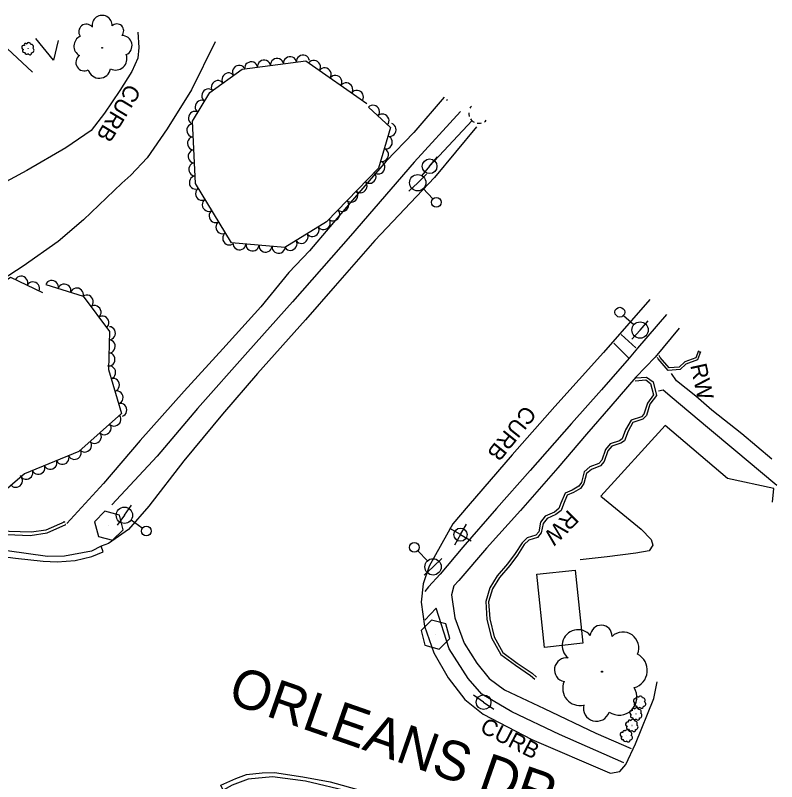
# Model space of a CAD drawing. Extents: x 1722896 to 1754269, y 648279 to 666297.
# Drawn here: x 1726702.6 to 1726935.6, y 658428.6 to 658663.1 of the extents above; entities that cross this region are included whole.
import ezdxf

# ---------------------------------------------------------------- set-up
doc = ezdxf.new("R2010")
doc.units = 0
for name, color, linetype in [('DESIGN - CENTERLINE - Proposed Text', 7, 'Continuous'), ('DESIGN - CONTOURS - Intermediate with optional Text', 7, 'Continuous'), ('DESIGN - PUBLIC HEARING - Shapes', 7, 'Continuous'), ('DESIGN - SCRATCH - User 1', 7, 'Continuous'), ('DESIGN - SHEET - Linework', 7, 'Continuous'), ('SURVEY - CENTERLINE - Preliminary Text', 7, 'Continuous'), ('SURVEY - DTM - Breaklines', 7, 'Continuous'), ('SURVEY - VEGETATION - Features with Text', 7, 'Continuous')]:
    doc.layers.add(name, color=color, linetype=linetype)

msp = doc.modelspace()

# ---------------------------------------------------------------- linework, layer by layer
at = {"layer": 'DESIGN - CENTERLINE - Proposed Text'}
for points in [[(1726696.9, 658655.81), (1726707.9, 658645.77)], [(1726833.89, 658638.08), (1726824.52, 658627.33), (1726816.14, 658618.55), (1726805.08, 658605.71), (1726792.64, 658591.1), (1726786.35, 658584.38), (1726777.69, 658573.93), (1726766.08, 658561.08), (1726754.24, 658548.1), (1726740.82, 658533.01), (1726729.63, 658519.78), (1726718.39, 658507.62)], [(1726834.86, 658637.31), (1726834.61, 658637.03)], [(1726888.06, 658565.4), (1726892.53, 658561.41)], [(1726890.43, 658558.05), (1726885.77, 658562.76)], [(1726911.9, 658560.11), (1726912.32, 658560.16)], [(1726934.1, 658527.29), (1726924.94, 658535.03), (1726915.75, 658542.24), (1726910.86, 658546.55), (1726904.99, 658551.21), (1726903.39, 658553.54)], [(1726899.44, 658548.2), (1726900.89, 658548.51), (1726903.67, 658546.19), (1726914.41, 658537.08), (1726923.14, 658529.86), (1726930.64, 658523.49), (1726935.61, 658519.37)], [(1726526.59, 658537.1), (1726525.3, 658537.11), (1726526.32, 658532.09), (1726527.85, 658528.94), (1726529.41, 658527.23), (1726533.34, 658525.23), (1726537.45, 658524.23), (1726556.14, 658522.16), (1726579.74, 658519.63), (1726602.55, 658516.42), (1726627.84, 658513.39), (1726649.7, 658510.72), (1726668.06, 658507.89), (1726688.75, 658505.07), (1726697.61, 658504.33), (1726707.12, 658503.88), (1726712.3, 658504.74), (1726718.03, 658507.32), (1726717.99, 658507.33)], [(1726717.73, 658508.11), (1726711.99, 658505.58), (1726707.59, 658504.91), (1726697.15, 658505.29), (1726677.53, 658507.38), (1726658.01, 658510.49), (1726632.24, 658514.13), (1726615.96, 658515.97), (1726595.56, 658518.62), (1726575.17, 658521.25), (1726552.96, 658523.64), (1726537.3, 658525.46), (1726532.61, 658526.65), (1726528.77, 658529.28), (1726527.23, 658532.59), (1726526.67, 658535.52), (1726526.59, 658537.1), (1726526.75, 658537.07)], [(1726717.33, 658508.17), (1726717.73, 658508.11)]]:
    msp.add_lwpolyline(points, dxfattribs=at)
msp.add_lwpolyline([(1726873.9, 658493.35), (1726876.3, 658470.92), (1726864.6, 658469.66), (1726862.19, 658492.1)], close=True, dxfattribs=at)
at = {"layer": 'DESIGN - CONTOURS - Intermediate with optional Text'}
for q in [(1726835.6, 658506.04), (1726840.72, 658507.42), (1726836.98, 658500.92), (1726842.09, 658502.3)]:
    msp.add_line((1726838.85, 658504.17), q, dxfattribs=at)
msp.add_circle((1726838.85, 658504.17), 2, dxfattribs=at)
at = {"layer": 'DESIGN - PUBLIC HEARING - Shapes'}
for p, q in [((1726731.17, 658506.92), (1726731.17, 658506.92)), ((1726831.13, 658473.6), (1726831.13, 658473.6))]:
    msp.add_line(p, q, dxfattribs=at)
for points in [[(1726734.44, 658510.18), (1726729.98, 658511.36), (1726726.81, 658508.13), (1726728.02, 658503.64), (1726732.37, 658502.48), (1726735.65, 658505.69), (1726734.44, 658510.18)], [(1726834.39, 658476.86), (1726829.93, 658478.04), (1726826.76, 658474.81), (1726827.97, 658470.32), (1726832.32, 658469.16), (1726835.6, 658472.37), (1726834.39, 658476.86)]]:
    msp.add_lwpolyline(points, dxfattribs=at)
at = {"layer": 'DESIGN - SCRATCH - User 1'}
for points in [[(1726912.32, 658560.16), (1726911.35, 658557.68), (1726907.83, 658556.38), (1726906.08, 658554.73), (1726902.45, 658554.46), (1726899.37, 658557.98), (1726899.16, 658558.38)], [(1726911.68, 658560.49), (1726910.83, 658558.29), (1726907.46, 658557.04), (1726905.78, 658555.46), (1726902.75, 658555.25), (1726899.95, 658558.44), (1726899.67, 658558.98)], [(1726892.29, 658551.26), (1726895.55, 658551.55), (1726897.02, 658550.49), (1726897.92, 658546.95), (1726896.05, 658544.47), (1726895, 658541.05), (1726894.2, 658540.23), (1726891.04, 658539.21), (1726889.36, 658536.22), (1726888.37, 658533.48), (1726887.5, 658532.9), (1726884.7, 658531.96), (1726883.2, 658530.28), (1726882.06, 658527.01), (1726881.2, 658525.95), (1726878.48, 658524.9), (1726876.65, 658523.38), (1726875.87, 658520.14), (1726875.04, 658518.99), (1726873.04, 658517.81), (1726870.85, 658516.84), (1726869.59, 658513.81), (1726868.93, 658512.13), (1726867.58, 658511.05), (1726864.81, 658509.81), (1726863.38, 658507.97), (1726862.79, 658505.08), (1726861.92, 658504.04), (1726859.27, 658503.21), (1726857.73, 658501.64), (1726855.61, 658498.4), (1726853.26, 658495.22), (1726850.07, 658491.59), (1726847.83, 658487.92), (1726846.57, 658483.71), (1726846.95, 658478.24), (1726848.35, 658472.57), (1726851.15, 658467.5), (1726855.65, 658464.18), (1726860.24, 658461.09), (1726861.6, 658459.91)], [(1726892.48, 658552.13), (1726895.79, 658552.42), (1726897.79, 658550.97), (1726898.81, 658546.73), (1726896.81, 658544.09), (1726895.74, 658540.61), (1726894.65, 658539.49), (1726891.6, 658538.51), (1726890.12, 658535.87), (1726889.06, 658532.94), (1726887.87, 658532.14), (1726885.18, 658531.23), (1726883.94, 658529.84), (1726882.8, 658526.6), (1726881.72, 658525.25), (1726878.9, 658524.16), (1726877.4, 658522.91), (1726876.64, 658519.79), (1726875.62, 658518.35), (1726873.42, 658517.06), (1726871.5, 658516.21), (1726870.36, 658513.5), (1726869.63, 658511.61), (1726868.01, 658510.33), (1726865.35, 658509.13), (1726864.16, 658507.61), (1726863.56, 658504.7), (1726862.4, 658503.31), (1726859.71, 658502.46), (1726858.38, 658501.11), (1726856.3, 658497.92), (1726853.91, 658494.7), (1726850.74, 658491.09), (1726848.6, 658487.58), (1726847.41, 658483.61), (1726847.79, 658478.37), (1726849.14, 658472.88), (1726851.8, 658468.07), (1726856.14, 658464.87), (1726860.76, 658461.76), (1726862.15, 658460.55)]]:
    msp.add_lwpolyline(points, dxfattribs=at)
at = {"layer": 'SURVEY - CENTERLINE - Preliminary Text'}
for points in [[(1726740.07, 658658), (1726740.44, 658653.35), (1726740.1, 658650.03), (1726738.23, 658645.95), (1726734.54, 658640.16), (1726729.86, 658633.24), (1726725.83, 658627.86), (1726718.06, 658622.62), (1726706.13, 658615.65), (1726695.86, 658610.15), (1726692.04, 658608.92), (1726690.74, 658609.12)], [(1726714.24, 658649.46), (1726708.85, 658656.09)], [(1726715.74, 658655.45), (1726714.24, 658649.46)], [(1726763.79, 658655.03), (1726756.5, 658640.29), (1726749.1, 658628.45), (1726742.99, 658619.54), (1726737.98, 658614.22), (1726735.22, 658611.72)], [(1726838.81, 658633.73), (1726824.62, 658618.22), (1726805.15, 658595.69), (1726787.42, 658575.49), (1726773.75, 658560.12), (1726758.4, 658542.77), (1726745.98, 658528.23), (1726732.13, 658513.34)], [(1726843.77, 658628.99), (1726830.89, 658613.54), (1726812.58, 658594.26), (1726800.45, 658580.34), (1726791.4, 658569.89), (1726776.7, 658553.5), (1726765.99, 658541.04), (1726754.22, 658526.72), (1726743.48, 658512.94), (1726737.19, 658505.75), (1726731.1, 658501.44)], [(1726735.22, 658611.72), (1726723.43, 658600.52), (1726715.74, 658593.91), (1726705, 658586.32), (1726692.08, 658577.96), (1726681.62, 658571.8), (1726674.06, 658568.05), (1726664.58, 658564.76), (1726645.61, 658560.03), (1726630.05, 658557.08), (1726616.29, 658555.5), (1726597.87, 658553.98), (1726580.16, 658553.27), (1726563.62, 658552.66), (1726547.63, 658552.96), (1726536.58, 658553.02), (1726533.49, 658553.17)], [(1726896.83, 658576.17), (1726882.61, 658559.91), (1726867.71, 658543.42), (1726854.66, 658528.61), (1726841.19, 658513.04), (1726836.46, 658507.47), (1726829.25, 658494.49), (1726827.38, 658489.13), (1726826.83, 658483.54), (1726827.85, 658476.11), (1726830.67, 658468.03), (1726835.07, 658460.38), (1726840.18, 658453.68), (1726845.83, 658449.2), (1726860.63, 658441.42), (1726884.49, 658431.28), (1726884.8, 658431.13)], [(1726901.89, 658571.58), (1726892.99, 658561.26), (1726890.45, 658558.24), (1726881.99, 658548.51), (1726872.83, 658538.16), (1726860.13, 658523.76), (1726849.86, 658512.14), (1726839.61, 658500.38), (1726832.61, 658492.08), (1726829.1, 658488.18), (1726827.93, 658486.77)], [(1726905.75, 658567.41), (1726898.45, 658558.53), (1726892.5, 658552.42), (1726884.87, 658543.54), (1726877.46, 658534.9), (1726868.62, 658524.66), (1726857.24, 658511.58), (1726846.77, 658500.03), (1726838.35, 658490.15), (1726836.78, 658488.51), (1726836.14, 658485.75), (1726837.16, 658478.7), (1726839.99, 658470.97), (1726843.87, 658464.85), (1726847.59, 658460.1), (1726852.33, 658456.71), (1726864.49, 658450.98), (1726880.31, 658443.37), (1726891.11, 658438.7)], [(1726934.37, 658514.07), (1726934.75, 658518.27), (1726920.57, 658521.37), (1726901.44, 658537.61), (1726881.8, 658515.97), (1726894.16, 658505.88), (1726897.22, 658502.67), (1726897.72, 658500.94), (1726896.59, 658499.23), (1726892.47, 658498.47), (1726883.71, 658497.38), (1726875.43, 658496.46)], [(1726728.9, 658500.65), (1726725.92, 658499.09), (1726717.69, 658497.6), (1726712.41, 658497.46), (1726700.07, 658499.18), (1726680.43, 658501.47), (1726657.94, 658504.14), (1726635.71, 658506.98), (1726611.67, 658510.08), (1726590.93, 658512.41), (1726569.71, 658514.96), (1726549.91, 658517.77), (1726535.26, 658519.69), (1726529.21, 658521.17), (1726529, 658521.35)], [(1726731.1, 658501.44), (1726728.9, 658500.65)], [(1726685.36, 658499.21), (1726702.61, 658496.94), (1726711.08, 658496.09), (1726715.37, 658495.84), (1726720.93, 658496.26), (1726726.06, 658497.49), (1726729.5, 658498.87)], [(1726729.5, 658498.87), (1726728.9, 658500.65)], [(1726888.84, 658434.28), (1726869.14, 658442.95), (1726854.59, 658449.95), (1726845.39, 658455.3), (1726841.19, 658460.09), (1726835.33, 658469.23), (1726831.4, 658481.63), (1726827.96, 658478.04)], [(1726889.44, 658433.83), (1726892.41, 658440.09), (1726898, 658454.01), (1726898.99, 658459.16)], [(1726884.8, 658431.13), (1726887.57, 658431.69), (1726889.44, 658433.83)], [(1726882.24, 658399.97), (1726865.25, 658406.11), (1726842.27, 658414.06), (1726823.86, 658419.71), (1726805.23, 658425.4), (1726791.45, 658428.71), (1726781.27, 658429.99), (1726773.86, 658429.31), (1726768.92, 658427.52), (1726766.17, 658425.97), (1726765.46, 658427.44), (1726770.04, 658429.56), (1726773.38, 658430.77), (1726778.15, 658431.31), (1726781.88, 658431.34), (1726790.57, 658429.99), (1726799, 658428.51), (1726808.86, 658425.7), (1726818.11, 658423.01), (1726827.64, 658420.05), (1726841.74, 658415.7), (1726859.59, 658409.82), (1726875.07, 658404.13), (1726882.76, 658401.33)]]:
    msp.add_lwpolyline(points, dxfattribs=at)
at = {"layer": 'SURVEY - DTM - Breaklines'}
for p, q in [((1726829.39, 658616.95), (1726842.4, 658630.93)), ((1726841.92, 658630.41), (1726842.4, 658630.93)), ((1726829.39, 658616.95), (1726831.8, 658619.82)), ((1726829.39, 658616.95), (1726826.97, 658614.08)), ((1726825.75, 658611.92), (1726828.47, 658614.5)), ((1726825.75, 658611.92), (1726823.03, 658609.34)), ((1726830.4, 658607.02), (1726827.47, 658610.11)), ((1726888.73, 658571.28), (1726891.92, 658568.47)), ((1726893.8, 658566.82), (1726896.28, 658569.63)), ((1726893.8, 658566.82), (1726891.32, 658564)), ((1726735.99, 658510.1), (1726738.18, 658513.15)), ((1726735.99, 658510.1), (1726733.8, 658507.06)), ((1726741.47, 658506.16), (1726738.02, 658508.64)), ((1726825.78, 658499.2), (1726828.72, 658496.12)), ((1726830.44, 658494.32), (1726833.16, 658496.91)), ((1726830.44, 658494.32), (1726827.73, 658491.73)), ((1726845.91, 658452.9), (1726842.8, 658455)), ((1726845.91, 658452.9), (1726849.01, 658450.8))]:
    msp.add_line(p, q, dxfattribs=at)
for centre, radius in [((1726829.39, 658616.95), 2.25), ((1726825.75, 658611.92), 2.5), ((1726831.43, 658605.93), 1.5), ((1726887.61, 658572.27), 1.5), ((1726893.8, 658566.82), 2.5), ((1726735.99, 658510.1), 2.5), ((1726742.69, 658505.29), 1.5), ((1726824.74, 658500.28), 1.5), ((1726830.44, 658494.32), 2.5), ((1726845.91, 658452.9), 2.25)]:
    msp.add_circle(centre, radius, dxfattribs=at)
for start_param, end_param in [(0, 0.255182), (0.730907, 1.085951), (1.352995, 1.815775), (2.156577, 2.588895), (2.883049, 3.125465)]:
    msp.add_ellipse((1726844.49, 658633.21), major_axis=(-2.29, 2.13), ratio=0.99992, start_param=start_param, end_param=end_param, dxfattribs=at)
at = {"layer": 'SURVEY - VEGETATION - Features with Text'}
for points in [[(1726810.65, 658635.08), (1726817.44, 658628.77), (1726813.75, 658616.4), (1726797.81, 658599.98), (1726785.09, 658592.03), (1726768.81, 658593.47), (1726757.75, 658611.65), (1726756.85, 658630.7), (1726762.12, 658639.51), (1726772.06, 658646.67), (1726791.49, 658649.22), (1726810.18, 658636.2)], [(1726711.89, 658580.7), (1726723.34, 658577.2), (1726731.38, 658566.32), (1726731.16, 658554.73), (1726735.12, 658541.28), (1726721.99, 658529.62), (1726705.44, 658522.82), (1726692.18, 658511.46), (1726681.59, 658508.96), (1726665.66, 658512.57), (1726640.5, 658520.36), (1726629.56, 658538.02), (1726630.78, 658550.05), (1726639.21, 658556.18), (1726660.1, 658561.65), (1726676.97, 658556.19), (1726686.52, 658563.54), (1726689.47, 658575.15), (1726701.11, 658583.02), (1726710.89, 658578.27)]]:
    msp.add_lwpolyline(points, dxfattribs=at)
for centre, radius in [((1726706.52, 658652.93), 0.022), ((1726729.19, 658653.22), 0.107), ((1726882.17, 658462.23), 0.169), ((1726893.72, 658452.88), 0.022), ((1726892.58, 658449.3), 0.022), ((1726891.35, 658445.76), 0.022), ((1726889.66, 658442.58), 0.022)]:
    msp.add_circle(centre, radius, dxfattribs=at)
for centre, radius, start, end in [((1726729.15, 658660.09), 3.06, 356.4149, 189.8346), ((1726724.33, 658658.11), 2.33, 39.0335, 216.3527), ((1726733.69, 658658.42), 2.1, 316.3942, 135.1398), ((1726723.82, 658653.73), 3.29, 114.3206, 241.1663), ((1726735.27, 658653.91), 3.06, 294.278, 91.0669), ((1726705.16, 658653.32), 0.629, 70.1013, 263.521), ((1726705.75, 658654.12), 0.433, 30.0806, 208.8263), ((1726706.73, 658654.17), 0.631, 7.9645, 164.7534), ((1726707.41, 658653.55), 0.719, 317.0172, 94.5414), ((1726705.27, 658652.26), 0.479, 112.72, 290.0391), ((1726706.11, 658651.9), 0.679, 188.007, 314.8527), ((1726707.08, 658651.58), 0.527, 198.1659, 13.1662), ((1726707.62, 658652.42), 0.714, 267.913, 63.7515), ((1726723.68, 658648.73), 2.56, 124.4795, 299.4798), ((1726733.27, 658649.88), 3.49, 243.3308, 20.855), ((1726728.29, 658647.36), 3.47, 194.2266, 350.0651), ((1726881.9, 658473.11), 3.33, 358.6658, 177.4115), ((1726874.8, 658470.24), 4.84, 38.6865, 232.1062), ((1726888.56, 658469.51), 4.85, 336.5497, 133.3386), ((1726871.28, 658462.78), 3.68, 81.3052, 258.6243), ((1726890.51, 658462.66), 5.52, 285.6024, 63.1267), ((1726875.34, 658457.1), 5.22, 156.5922, 283.4379), ((1726887.36, 658454.41), 5.49, 236.4982, 32.3367), ((1726892.96, 658454.07), 0.433, 30.0806, 208.8263), ((1726893.94, 658454.12), 0.631, 7.9645, 164.7534), ((1726894.62, 658453.49), 0.719, 317.0172, 94.5414), ((1726880.49, 658451.1), 4.05, 166.7511, 341.7514), ((1726892.36, 658453.27), 0.629, 70.1013, 263.521), ((1726892.48, 658452.2), 0.479, 112.72, 290.0391), ((1726894.83, 658452.36), 0.714, 267.913, 63.7515), ((1726891.22, 658449.69), 0.629, 70.1013, 263.521), ((1726891.81, 658450.49), 0.433, 30.0806, 208.8263), ((1726892.79, 658450.54), 0.631, 7.9645, 164.7534), ((1726893.31, 658451.85), 0.679, 188.007, 314.8527), ((1726893.47, 658449.92), 0.719, 317.0172, 94.5414), ((1726894.29, 658451.53), 0.527, 198.1659, 13.1662), ((1726890.59, 658446.96), 0.433, 30.0806, 208.8263), ((1726891.33, 658448.62), 0.479, 112.72, 290.0391), ((1726891.57, 658447.01), 0.631, 7.9645, 164.7534), ((1726892.17, 658448.27), 0.679, 188.007, 314.8527), ((1726893.14, 658447.95), 0.527, 198.1659, 13.1662), ((1726893.68, 658448.79), 0.714, 267.913, 63.7515), ((1726889.99, 658446.15), 0.629, 70.1013, 263.521), ((1726890.11, 658445.09), 0.479, 112.72, 290.0391), ((1726892.25, 658446.38), 0.719, 317.0172, 94.5414), ((1726892.46, 658445.25), 0.714, 267.913, 63.7515), ((1726888.3, 658442.97), 0.629, 70.1013, 263.521), ((1726888.9, 658443.77), 0.433, 30.0806, 208.8263), ((1726889.88, 658443.82), 0.631, 7.9645, 164.7534), ((1726890.94, 658444.73), 0.679, 188.007, 314.8527), ((1726890.56, 658443.19), 0.719, 317.0172, 94.5414), ((1726890.77, 658442.06), 0.714, 267.913, 63.7515), ((1726891.92, 658444.41), 0.527, 198.1659, 13.1662), ((1726888.42, 658441.9), 0.479, 112.72, 290.0391), ((1726889.25, 658441.55), 0.679, 188.007, 314.8527), ((1726890.23, 658441.23), 0.527, 198.1659, 13.1662)]:
    msp.add_arc(centre, radius, start, end, dxfattribs=at)
for centre, major_axis in [((1726774.77, 658647.02), (1.98, 0.26)), ((1726778.73, 658647.54), (1.98, 0.26)), ((1726782.7, 658648.07), (1.98, 0.26)), ((1726786.66, 658648.59), (1.98, 0.26)), ((1726790.63, 658649.11), (1.98, 0.26)), ((1726794.06, 658647.43), (1.64, -1.14)), ((1726771.03, 658645.93), (1.62, 1.17)), ((1726797.34, 658645.14), (1.64, -1.14)), ((1726767.78, 658643.59), (1.62, 1.17)), ((1726800.62, 658642.86), (1.64, -1.14)), ((1726764.54, 658641.25), (1.62, 1.17)), ((1726803.91, 658640.57), (1.64, -1.14)), ((1726761.6, 658638.63), (1.03, 1.72)), ((1726807.19, 658638.28), (1.64, -1.14)), ((1726759.54, 658635.2), (1.03, 1.72)), ((1726812.11, 658633.72), (1.46, -1.36)), ((1726757.49, 658631.77), (1.03, 1.72)), ((1726815.04, 658631), (1.46, -1.36)), ((1726756.98, 658627.94), (-0.09, 2)), ((1726817.23, 658628.07), (-0.57, -1.92)), ((1726757.17, 658623.95), (-0.09, 2)), ((1726816.08, 658624.24), (-0.57, -1.92)), ((1726757.36, 658619.95), (-0.09, 2)), ((1726814.94, 658620.4), (-0.57, -1.92)), ((1726813.8, 658616.57), (-0.57, -1.92)), ((1726757.55, 658615.96), (-0.09, 2)), ((1726757.74, 658611.96), (-0.09, 2)), ((1726811.09, 658613.66), (-1.39, -1.43)), ((1726808.3, 658610.79), (-1.39, -1.43)), ((1726759.67, 658608.5), (-1.04, 1.71)), ((1726805.51, 658607.92), (-1.39, -1.43)), ((1726761.74, 658605.08), (-1.04, 1.71)), ((1726802.73, 658605.05), (-1.39, -1.43)), ((1726763.82, 658601.66), (-1.04, 1.71)), ((1726799.94, 658602.18), (-1.39, -1.43)), ((1726765.9, 658598.25), (-1.04, 1.71)), ((1726797.01, 658599.48), (-1.7, -1.06)), ((1726793.62, 658597.36), (-1.7, -1.06)), ((1726767.98, 658594.83), (-1.04, 1.71)), ((1726790.23, 658595.24), (-1.7, -1.06)), ((1726771.21, 658593.26), (-1.99, 0.18)), ((1726775.19, 658592.9), (-1.99, 0.18)), ((1726779.17, 658592.55), (-1.99, 0.18)), ((1726786.84, 658593.12), (-1.7, -1.06)), ((1726783.16, 658592.2), (-1.99, 0.18)), ((1726704.46, 658581.39), (1.8, -0.87)), ((1726708.06, 658579.64), (1.8, -0.87)), ((1726713.8, 658580.12), (1.91, -0.59)), ((1726717.63, 658578.95), (1.91, -0.59)), ((1726721.45, 658577.78), (1.91, -0.59)), ((1726724.55, 658575.57), (1.19, -1.61)), ((1726726.92, 658572.35), (1.19, -1.61)), ((1726729.3, 658569.14), (1.19, -1.61)), ((1726731.37, 658565.82), (-0.04, -2)), ((1726731.29, 658561.82), (-0.04, -2)), ((1726731.22, 658557.82), (-0.04, -2)), ((1726731.42, 658553.86), (0.57, -1.92)), ((1726732.55, 658550.02), (0.57, -1.92)), ((1726733.68, 658546.19), (0.57, -1.92)), ((1726734.81, 658542.35), (0.57, -1.92)), ((1726732.97, 658539.37), (-1.5, -1.33)), ((1726729.97, 658536.71), (-1.5, -1.33)), ((1726726.98, 658534.05), (-1.5, -1.33)), ((1726723.99, 658531.4), (-1.5, -1.33)), ((1726720.77, 658529.11), (-1.85, -0.76)), ((1726717.07, 658527.59), (-1.85, -0.76)), ((1726709.67, 658524.55), (-1.85, -0.76)), ((1726713.37, 658526.07), (-1.85, -0.76)), ((1726705.97, 658523.03), (-1.85, -0.76)), ((1726702.84, 658520.59), (-1.52, -1.3))]:
    msp.add_ellipse(centre, major_axis=major_axis, ratio=0.940188, start_param=0, end_param=3.141593, dxfattribs=at)

# ---------------------------------------------------------------- texts
at = {"layer": 'DESIGN - SCRATCH - User 1'}
for s, rotation, p in [('CURB', 238.9983, (1726737.01, 658642.55)), ('RW', 282.3541, (1726909.14, 658556.01)), ('CURB', 231.3411, (1726858.57, 658544.09)), ('RW', 225.1578, (1726871.91, 658512.03)), ('CURB', 332.7166, (1726844.46, 658443.95))]:
    msp.add_text(s, height=5, rotation=rotation, dxfattribs=at).set_placement(p)
at = {"layer": 'DESIGN - SHEET - Linework'}
msp.add_text('ORLEANS DR.', height=12, rotation=340.7578, dxfattribs=at).set_placement((1726767.15, 658452.92))

doc.saveas('drawing.dxf')
